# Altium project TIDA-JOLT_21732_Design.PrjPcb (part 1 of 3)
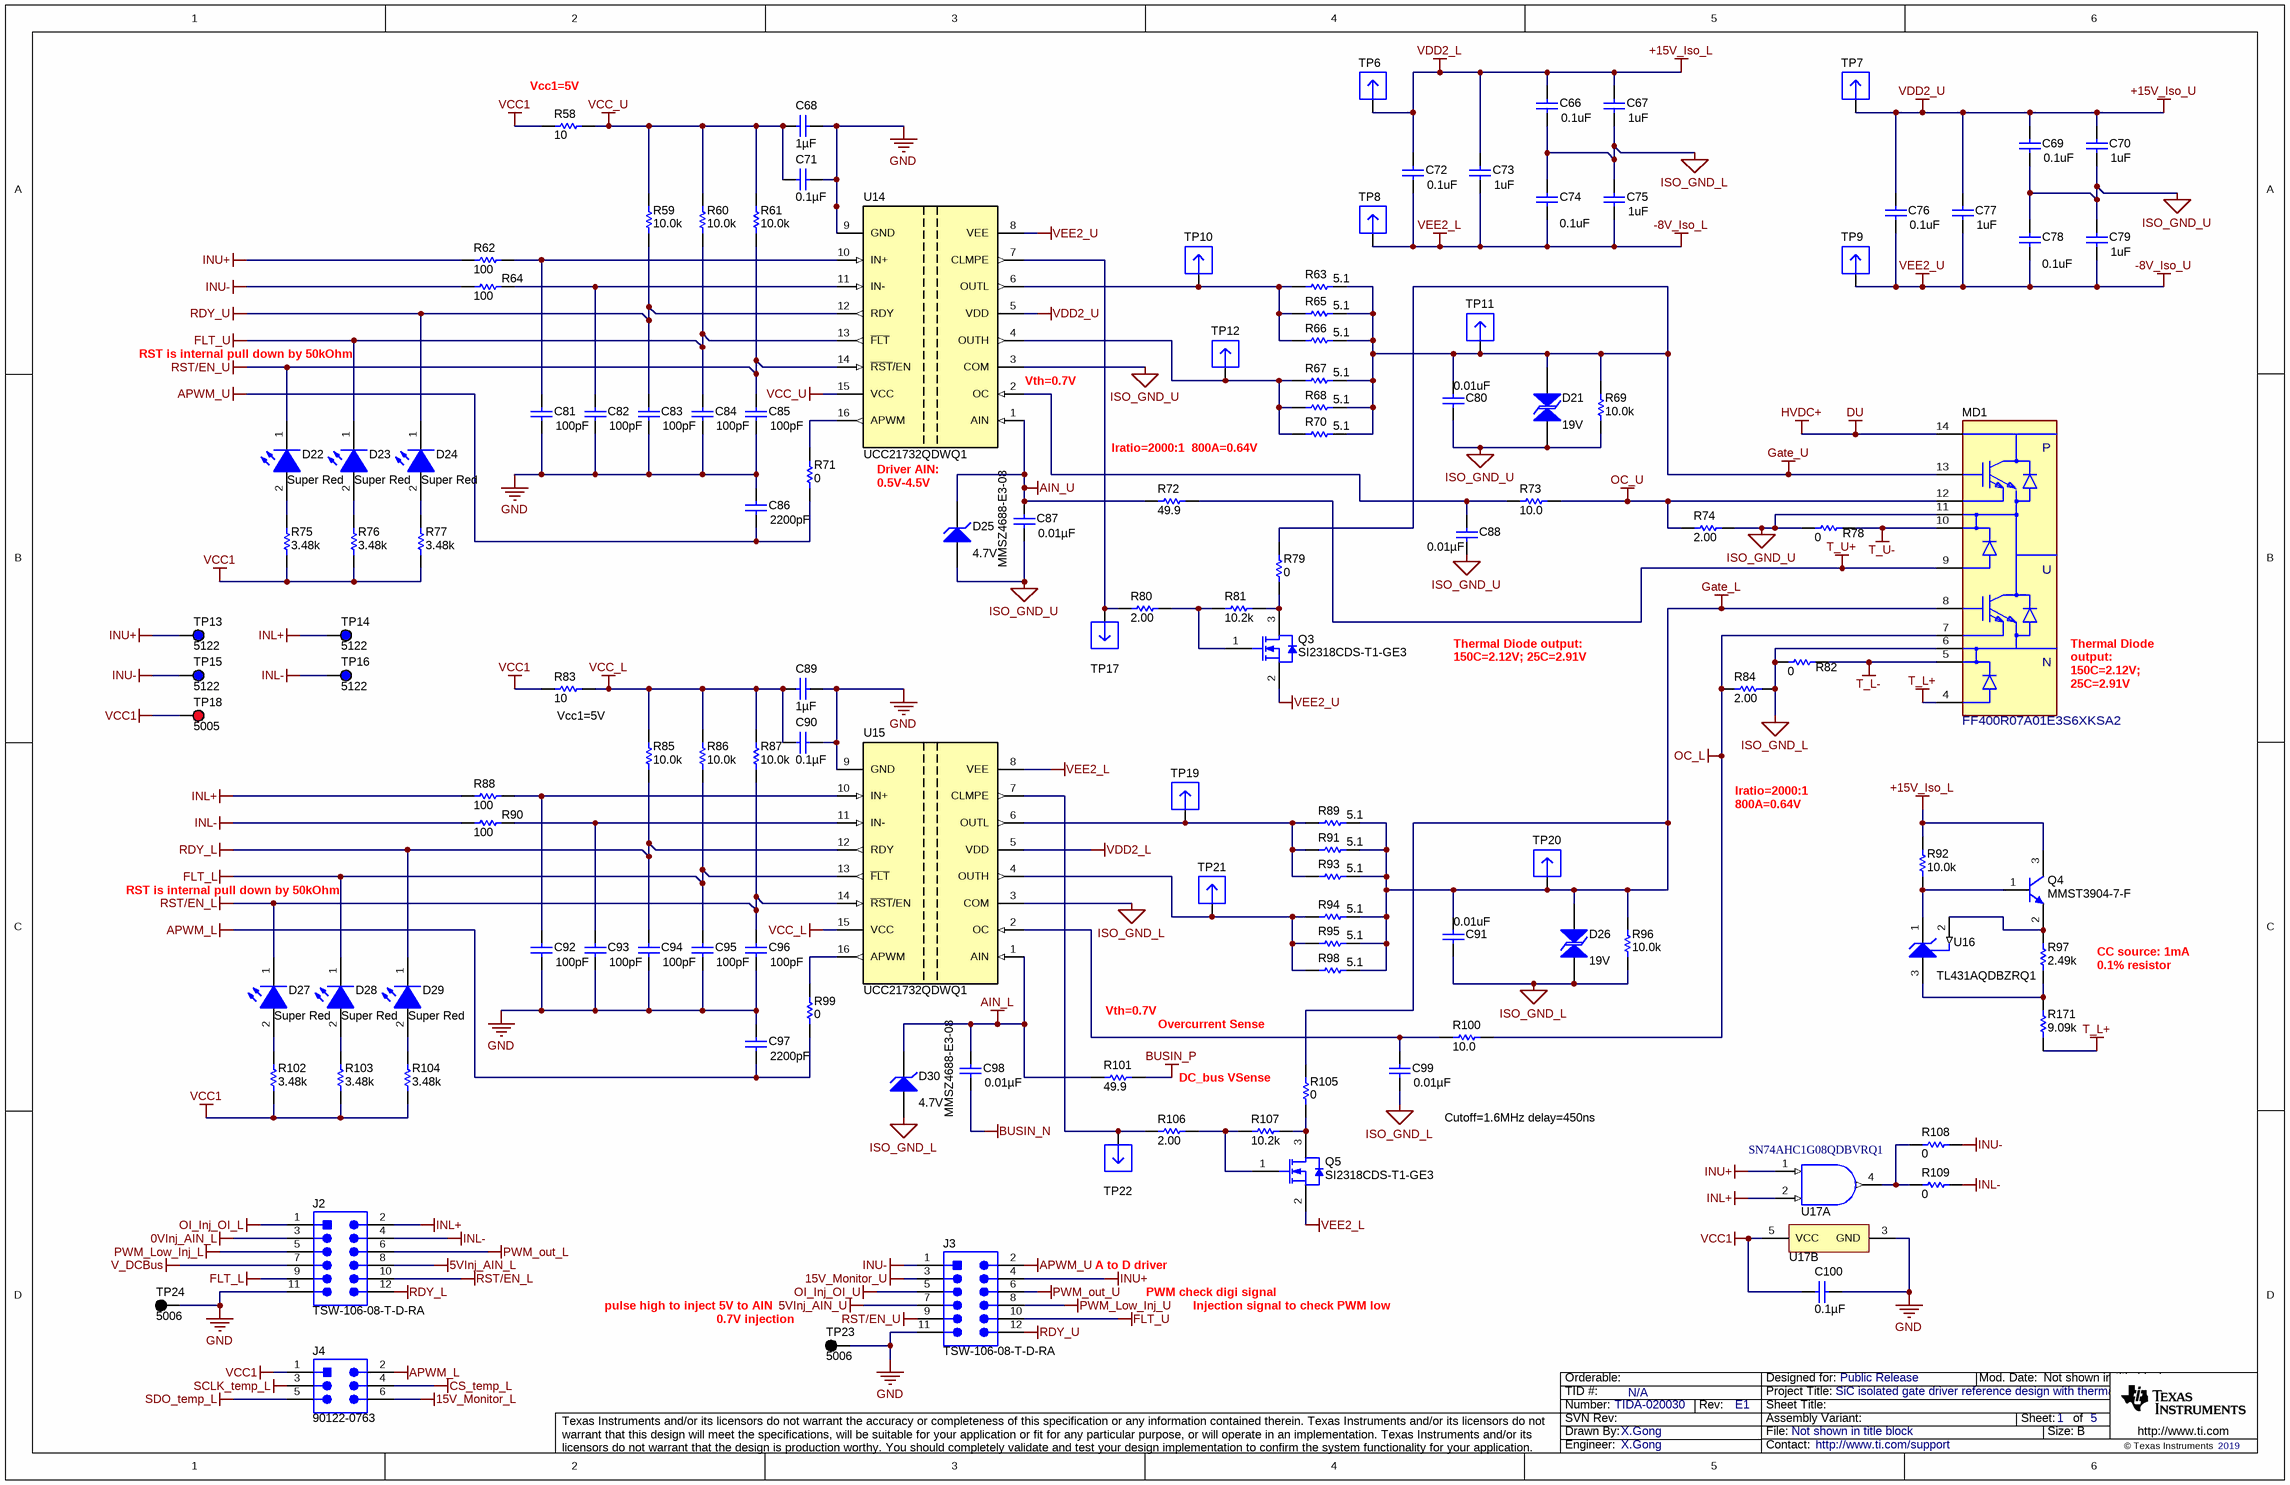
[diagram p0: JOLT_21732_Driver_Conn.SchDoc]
CopyrightYear: 2019; PCB_Layout: X.Gong; PCB_Rev: E1; PRJ_Customer: Public Release; PRJ_Engineer: X.Gong; PRJ_Number: TIDA-020030; PRJ_Title: SiC isolated gate driver reference design with thermal diode and sensing FET; SCH_Rev: E1; TechSupport: http://www.ti.com/support; TID: N/A
5 sheets, 442 parts. Net scope: global (net labels, ports and power ports of the same name join across sheets).
Board file: TIDA-JOLT_21732_Design_PCB.PcbDoc
Sheets:
  JOLT_21732_Driver_Conn.SchDoc
  JOLT_21732_OI_AIN_PWM_check.SchDoc
  JOLT_21732_DCbus_Thermal_LS.SchDoc
  JOLT_21732_Supply_Bias.SchDoc
  JOLT_21732_Design_EVM_Hardware.SchDoc

## Sheet JOLT_21732_Driver_Conn.SchDoc
size 431 x 279 mm; Date: Not shown in title block; ApprovedBy: Not shown in title block; CheckedBy: Not shown in title block; Author: Not shown in title block; CompanyName: Not shown in title block; DrawnBy: X.Gong; Engineer: Not shown in title block; Organization: Not shown in title block; Address1: Not shown in title block; Address2: Not shown in title block; Address3: Not shown in title block; Address4: Not shown in title block; DocumentNumber: 1; Revision: Use project parameter SCH_Rev; SheetNumber: 1; SheetTotal: 5; PageSetup: Record=PageOptions¦CenterHorizontal=True¦CenterVertical=True¦PrintScale=1.00¦XCorrection=1.00¦YCorrection=1.00¦PrintKind=0¦BorderSize=5000000¦LeftOffset=0¦BottomOffset=0¦Orientation=2¦PaperLength=1000¦PaperWidth=1000¦Scale=100¦PaperSource=15¦PrintQuality=600¦MediaType=1¦DitherType=10¦PaperKind=Letter¦PrintScaleMode=1

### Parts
(Parts that share a designator on the sheet are numbered #1, #2 ... from top to bottom, then left to right.)
C66  ValueDisplayed: 0.1uF  [1206]  (hidden comment: C1206C104J5RACTU)
C67  ValueDisplayed: 1uF  [1206_180]  (hidden comment: C3216X7R1H105K160AB)
C68  ValueDisplayed: 1µF  [0603]  (hidden comment: GRM188R71E105KA12D)
C69  ValueDisplayed: 0.1uF  [1206]  (hidden comment: C1206C104J5RACTU)
C70  ValueDisplayed: 1uF  [1206_180]  (hidden comment: C3216X7R1H105K160AB)
C71  ValueDisplayed: 0.1µF  [0603]  (hidden comment: GRM188R71H104KA93D)
C72  ValueDisplayed: 0.1uF  [1206]  (hidden comment: C1206C104J5RACTU)
C73  ValueDisplayed: 1uF  [1206_180]  (hidden comment: C3216X7R1H105K160AB)
C74  ValueDisplayed: 0.1uF  [0402]  (hidden comment: GCM155R71C104KA55D)
C75  ValueDisplayed: 1uF  [0603]  (hidden comment: UMK107AB7105KA-T)
C76  ValueDisplayed: 0.1uF  [1206]  (hidden comment: C1206C104J5RACTU)
C77  ValueDisplayed: 1uF  [1206_180]  (hidden comment: C3216X7R1H105K160AB)
C78  ValueDisplayed: 0.1uF  [0402]  (hidden comment: GCM155R71C104KA55D)
C79  ValueDisplayed: 1uF  [0603]  (hidden comment: UMK107AB7105KA-T)
C80  ValueDisplayed: 0.01uF  [0603]  (hidden comment: GRM188R71H103KA01D)
C81  ValueDisplayed: 100pF  [0402]  (hidden comment: CC0402JRNPO9BN101)
C82  ValueDisplayed: 100pF  [0402]  (hidden comment: CC0402JRNPO9BN101)
C83  ValueDisplayed: 100pF  [0402]  (hidden comment: CC0402JRNPO9BN101)
C84  ValueDisplayed: 100pF  [0402]  (hidden comment: CC0402JRNPO9BN101)
C85  ValueDisplayed: 100pF  [0402]  (hidden comment: CC0402JRNPO9BN101)
C86  ValueDisplayed: 2200pF  [0402]  (hidden comment: GRM155R71C222KA01D)
C87  ValueDisplayed: 0.01µF  [0603]  (hidden comment: SR0603X7R103K1NT95(F)#M123A)
C88  ValueDisplayed: 0.01µF  [0603]  (hidden comment: SR0603X7R103K1NT95(F)#M123A)
C89  ValueDisplayed: 1µF  [0603]  (hidden comment: GRM188R71E105KA12D)
C90  ValueDisplayed: 0.1µF  [0603]  (hidden comment: GRM188R71H104KA93D)
C91  ValueDisplayed: 0.01uF  [0603]  (hidden comment: GRM188R71H103KA01D)
C92  ValueDisplayed: 100pF  [0402]  (hidden comment: CC0402JRNPO9BN101)
C93  ValueDisplayed: 100pF  [0402]  (hidden comment: CC0402JRNPO9BN101)
C94  ValueDisplayed: 100pF  [0402]  (hidden comment: CC0402JRNPO9BN101)
C95  ValueDisplayed: 100pF  [0402]  (hidden comment: CC0402JRNPO9BN101)
C96  ValueDisplayed: 100pF  [0402]  (hidden comment: CC0402JRNPO9BN101)
C97  ValueDisplayed: 2200pF  [0402]  (hidden comment: GRM155R71C222KA01D)
C98  ValueDisplayed: 0.01µF  [0603]  (hidden comment: SR0603X7R103K1NT95(F)#M123A)
C99  ValueDisplayed: 0.01µF  [0603]  (hidden comment: SR0603X7R103K1NT95(F)#M123A)
C100  ValueDisplayed: 0.1µF  [0603]  (hidden comment: GRM188R71H104KA93D)
D21  value 19V  [SMB]  (hidden comment: SMBJ20CA)
D22  value Super Red  [WL-SMCW_RED]  (hidden comment: 150060SS75000)
D23  value Super Red  [WL-SMCW_RED]  (hidden comment: 150060SS75000)
D24  value Super Red  [WL-SMCW_RED]  (hidden comment: 150060SS75000)
D25  MMSZ4688-E3-08  value 4.7V  [SOD-123]
D26  value 19V  [SMB]  (hidden comment: SMBJ20CA)
D27  value Super Red  [WL-SMCW_RED]  (hidden comment: 150060SS75000)
D28  value Super Red  [WL-SMCW_RED]  (hidden comment: 150060SS75000)
D29  value Super Red  [WL-SMCW_RED]  (hidden comment: 150060SS75000)
D30  MMSZ4688-E3-08  value 4.7V  [SOD-123]
J2  TSW-106-08-T-D-RA  [AB12-DEST]
J3  TSW-106-08-T-D-RA  [AB12-DEST]
J4  90122-0763  [Molex_90122-0763]
MD1  FF400R07A01E3S6XKSA2  [FP-FF400R07A01E3S6XKSA2_PG-MDIP-14-MFG]
Q3  SI2318CDS-T1-GE3  [SOT-23]
Q4  MMST3904-7-F  [SOT-323]
Q5  SI2318CDS-T1-GE3  [SOT-23]
R58  ValueDisplayed: 10  [0805_HV]  (hidden comment: CRCW080510R0JNEA)
R59  ValueDisplayed: 10.0k  [0402]  (hidden comment: RMCF0402FT10K0)
R60  ValueDisplayed: 10.0k  [0402]  (hidden comment: RMCF0402FT10K0)
R61  ValueDisplayed: 10.0k  [0402]  (hidden comment: RMCF0402FT10K0)
R62  ValueDisplayed: 100  [0402]  (hidden comment: Resistor)
R63  ValueDisplayed: 5.1  [2010]  (hidden comment: CRCW20105R10JNEF)
R64  ValueDisplayed: 100  [0402]  (hidden comment: Resistor)
R65  ValueDisplayed: 5.1  [2010]  (hidden comment: CRCW20105R10JNEF)
R66  ValueDisplayed: 5.1  [2010]  (hidden comment: CRCW20105R10JNEF)
R67  ValueDisplayed: 5.1  [2010]  (hidden comment: CRCW20105R10JNEF)
R68  ValueDisplayed: 5.1  [2010]  (hidden comment: CRCW20105R10JNEF)
R69  ValueDisplayed: 10.0k  [0603]  (hidden comment: CRCW060310K0FKEA)
R70  ValueDisplayed: 5.1  [2010]  (hidden comment: CRCW20105R10JNEF)
R71  ValueDisplayed: 0  [0603]  (hidden comment: CRCW06030000Z0EA)
R72  ValueDisplayed: 49.9  [0603]  (hidden comment: CRCW060349R9FKEA)
R73  ValueDisplayed: 10.0  [0603]  (hidden comment: TNPW060310R0BEEA)
R74  ValueDisplayed: 2.00  [1206]  (hidden comment: CRCW12062R00FKEA)
R75  ValueDisplayed: 3.48k  [0603]  (hidden comment: CRCW06033K48FKEA)
R76  ValueDisplayed: 3.48k  [0603]  (hidden comment: CRCW06033K48FKEA)
R77  ValueDisplayed: 3.48k  [0603]  (hidden comment: CRCW06033K48FKEA)
R78  ValueDisplayed: 0  [0402]  (hidden comment: CRCW04020000Z0ED)
R79  ValueDisplayed: 0  [0603]  (hidden comment: CRCW06030000Z0EA)
R80  ValueDisplayed: 2.00  [1206]  (hidden comment: CRCW12062R00FKEA)
R81  ValueDisplayed: 10.2k  [0603]  (hidden comment: CRCW060310K2FKEA)
R82  ValueDisplayed: 0  [0402]  (hidden comment: CRCW04020000Z0ED)
R83  ValueDisplayed: 10  [0805_HV]  (hidden comment: CRCW080510R0JNEA)
R84  ValueDisplayed: 2.00  [1206]  (hidden comment: CRCW12062R00FKEA)
R85  ValueDisplayed: 10.0k  [0402]  (hidden comment: RMCF0402FT10K0)
R86  ValueDisplayed: 10.0k  [0402]  (hidden comment: RMCF0402FT10K0)
R87  ValueDisplayed: 10.0k  [0402]  (hidden comment: RMCF0402FT10K0)
R88  ValueDisplayed: 100  [0402]  (hidden comment: Resistor)
R89  ValueDisplayed: 5.1  [2010]  (hidden comment: CRCW20105R10JNEF)
R90  ValueDisplayed: 100  [0402]  (hidden comment: Resistor)
R91  ValueDisplayed: 5.1  [2010]  (hidden comment: CRCW20105R10JNEF)
R92  ValueDisplayed: 10.0k  [0805_HV]  (hidden comment: CRCW080510K0FKEA)
R93  ValueDisplayed: 5.1  [2010]  (hidden comment: CRCW20105R10JNEF)
R94  ValueDisplayed: 5.1  [2010]  (hidden comment: CRCW20105R10JNEF)
R95  ValueDisplayed: 5.1  [2010]  (hidden comment: CRCW20105R10JNEF)
R96  ValueDisplayed: 10.0k  [0603]  (hidden comment: CRCW060310K0FKEA)
R97  ValueDisplayed: 2.49k  [0805_HV]  (hidden comment: RT0805BRD072K49L)
R98  ValueDisplayed: 5.1  [2010]  (hidden comment: CRCW20105R10JNEF)
R99  ValueDisplayed: 0  [0603]  (hidden comment: CRCW06030000Z0EA)
R100  ValueDisplayed: 10.0  [0603]  (hidden comment: TNPW060310R0BEEA)
R101  ValueDisplayed: 49.9  [0603]  (hidden comment: CRCW060349R9FKEA)
R102  ValueDisplayed: 3.48k  [0603]  (hidden comment: CRCW06033K48FKEA)
R103  ValueDisplayed: 3.48k  [0603]  (hidden comment: CRCW06033K48FKEA)
R104  ValueDisplayed: 3.48k  [0603]  (hidden comment: CRCW06033K48FKEA)
R105  ValueDisplayed: 0  [0603]  (hidden comment: CRCW06030000Z0EA)
R106  ValueDisplayed: 2.00  [1206]  (hidden comment: CRCW12062R00FKEA)
R107  ValueDisplayed: 10.2k  [0603]  (hidden comment: CRCW060310K2FKEA)
R108  ValueDisplayed: 0  [0603]  (hidden comment: ERJ-3GEY0R00V)
R109  ValueDisplayed: 0  [0603]  (hidden comment: ERJ-3GEY0R00V)
R171  ValueDisplayed: 9.09k  [0603]  (hidden comment: CRCW06039K09FKEA)
TP6  0508-0-00-15-00-00-03-0  [Mill-Max_0508-0-00-15-00-00-03-0]  (value not drawn)
TP7  0508-0-00-15-00-00-03-0  [Mill-Max_0508-0-00-15-00-00-03-0]  (value not drawn)
TP8  0508-0-00-15-00-00-03-0  [Mill-Max_0508-0-00-15-00-00-03-0]  (value not drawn)
TP9  0508-0-00-15-00-00-03-0  [Mill-Max_0508-0-00-15-00-00-03-0]  (value not drawn)
TP10  0508-0-00-15-00-00-03-0  [Mill-Max_0508-0-00-15-00-00-03-0]  (value not drawn)
TP11  0508-0-00-15-00-00-03-0  [Mill-Max_0508-0-00-15-00-00-03-0]  (value not drawn)
TP12  0508-0-00-15-00-00-03-0  [Mill-Max_0508-0-00-15-00-00-03-0]  (value not drawn)
TP13  5122  [Keystone5122]
TP14  5122  [Keystone5122]
TP15  5122  [Keystone5122]
TP16  5122  [Keystone5122]
TP17  0508-0-00-15-00-00-03-0  [Mill-Max_0508-0-00-15-00-00-03-0]  (value not drawn)
TP18  5005  [Keystone5005]
TP19  0508-0-00-15-00-00-03-0  [Mill-Max_0508-0-00-15-00-00-03-0]  (value not drawn)
TP20  0508-0-00-15-00-00-03-0  [Mill-Max_0508-0-00-15-00-00-03-0]  (value not drawn)
TP21  0508-0-00-15-00-00-03-0  [Mill-Max_0508-0-00-15-00-00-03-0]  (value not drawn)
TP22  0508-0-00-15-00-00-03-0  [Mill-Max_0508-0-00-15-00-00-03-0]  (value not drawn)
TP23  5006  [Keystone5006]
TP24  5006  [Keystone5006]
U14  UCC21732QDWQ1  [DW0016B_HV]
U15  UCC21732QDWQ1  [DW0016B_HV]
U16  TL431AQDBZRQ1  [DBZ0003A_N]
U17#1  SN74AHC1G08QDBVRQ1  [DBV0005A_N]  (part A of 2)
U17#2  SN74AHC1G08QDBVRQ1  [DBV0005A_N]  (value not drawn)  (part B of 2)

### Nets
0VInj_AIN_L: J2.3
5VInj_AIN_L: J2.8
5VInj_AIN_U: J3.7
15V_Monitor_L: J4.6
15V_Monitor_U: J3.3
+15V_Iso_L: C66.1 C67.1 C72.1 C73.1 Q4.3(C) R92.2 TP6.1 U15.5(VDD)  [also labelled VDD2_L]
+15V_Iso_U: C69.1 C70.1 C76.1 C77.1 TP7.1 U14.5(VDD)  [also labelled VDD2_U]
-8V_Iso_L: C72.2 C73.2 C74.2 C75.2 Q5.2(S) TP8.1 U15.8(VEE)  [also labelled VEE2_L]
-8V_Iso_U: C76.2 C77.2 C78.2 C79.2 Q3.2(S) TP9.1 U14.8(VEE)  [also labelled VEE2_U]
AIN_L: C98.1 D30.1(K) R101.2 U15.1(AIN)
AIN_U: C87.1 D25.1(K) R72.2 U14.1(AIN)
APWM_L: C97.1 J4.2 R99.1
APWM_U: C86.1 J3.2 R71.1
BUSIN_N: C98.2
BUSIN_P: R101.1
CS_temp_L: J4.4
DU: MD1.14(PS)  [also labelled HVDC+]
FLT_L: C95.1 D28.1(K) J2.9 R86.1 U15.13(~{FLT})
FLT_U: C84.1 D23.1(K) J3.10 R60.1 U14.13(~{FLT})
Gate_L: C91.1 D26.2 MD1.8(GL) R89.2 R91.2 R93.2 R94.2 R95.2 R96.2 R98.2 R105.2 TP20.1
Gate_U: C80.1 D21.2 MD1.13(GH) R63.2 R65.2 R66.2 R67.2 R68.2 R69.2 R70.2 R79.2 TP11.1
GND: C68.1 C71.2 C81.2 C82.2 C83.2 C84.2 C85.2 C86.2 C89.1 C90.2 C92.2 C93.2 C94.2 C95.2 C96.2 C97.2 C100.2 J2.11 J3.11 TP23.1 TP24.1 U14.9(GND) U15.9(GND) U17#2.3(GND)
INL+: J2.2 R88.2 TP14.1 U17#1.2(B)
INL-: J2.4 R90.2 R109.2 TP16.1
INU+: J3.4 R62.2 TP13.1 U17#1.1(A)
INU-: J3.1 R64.2 R108.2 TP15.1
ISO_GND_L: C66.2 C67.2 C74.1 C75.1 C91.2 C99.2 D26.1 D30.2(A) MD1.6(EL) R82.1 R84.1 R96.1 U15.3(COM)
ISO_GND_U: C69.2 C70.2 C78.1 C79.1 C80.2 C87.2 C88.2 D21.1 D25.2(A) MD1.11(EH) R69.1 R74.1 R78.1 U14.3(COM)
OC_L: MD1.7(CSL) R84.2 R100.2
OC_U: MD1.12(CSH) R73.2 R74.2
OI_Inj_OI_L: J2.1
OI_Inj_OI_U: J3.5
PWM_Low_Inj_L: J2.5
PWM_Low_Inj_U: J3.8
PWM_out_L: J2.6
PWM_out_U: J3.6
RDY_L: C94.1 D29.1(K) J2.12 R85.1 U15.12(RDY)
RDY_U: C83.1 D24.1(K) J3.12 R59.1 U14.12(RDY)
RST/EN_L: C96.1 D27.1(K) J2.10 R87.1 U15.14(~{RST}/EN)
RST/EN_U: C85.1 D22.1(K) J3.9 R61.1 U14.14(~{RST}/EN)
SCLK_temp_L: J4.3
SDO_temp_L: J4.5
T_L+: MD1.4(T+L) R171.1
T_L-: MD1.5(T-L) R82.2
T_U+: MD1.9(T+H) R72.1
T_U-: MD1.10(T-H) R78.2
V_DCBus: J2.7
VCC1: C100.1 J4.1 R58.1 R75.1 R76.1 R77.1 R83.1 R102.1 R103.1 R104.1 TP18.1 U17#2.5(VCC)
VCC_L: C89.2 C90.1 R83.2 R85.2 R86.2 R87.2 U15.15(VCC)
VCC_U: C68.2 C71.1 R58.2 R59.2 R60.2 R61.2 U14.15(VCC)
NetC81_1: C81.1 R62.1 U14.10(IN+)
NetC82_1: C82.1 R64.1 U14.11(IN-)
NetC88_1: C88.1 R73.1 U14.2(OC)
NetC92_1: C92.1 R88.1 U15.10(IN+)
NetC93_1: C93.1 R90.1 U15.11(IN-)
NetC99_1: C99.1 R100.1 U15.2(OC)
NetD22_2: D22.2(A) R75.2
NetD23_2: D23.2(A) R76.2
NetD24_2: D24.2(A) R77.2
NetD27_2: D27.2(A) R102.2
NetD28_2: D28.2(A) R103.2
NetD29_2: D29.2(A) R104.2
NetQ3_1: Q3.1(G) R80.1 R81.1
NetQ3_3: Q3.3(D) R79.1 R81.2
NetQ4_1: Q4.1(B) R92.1 U16.1(CATHODE)
NetQ4_2: Q4.2(E) R97.2 U16.2(REF)
NetQ5_1: Q5.1(G) R106.1 R107.1
NetQ5_3: Q5.3(D) R105.1 R107.2
NetR63_1: R63.1 R65.1 R66.1 TP10.1 U14.6(OUTL)
NetR67_1: R67.1 R68.1 R70.1 TP12.1 U14.4(OUTH)
NetR71_2: R71.2 U14.16(APWM)
NetR80_2: R80.2 TP17.1 U14.7(CLMPE)
NetR89_1: R89.1 R91.1 R93.1 TP19.1 U15.6(OUTL)
NetR94_1: R94.1 R95.1 R98.1 TP21.1 U15.4(OUTH)
NetR97_1: R97.1 R171.2 U16.3(ANODE)
NetR99_2: R99.2 U15.16(APWM)
NetR106_2: R106.2 TP22.1 U15.7(CLMPE)
NetR108_1: R108.1 R109.1 U17#1.4(Y)

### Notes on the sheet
- (near R58) Vcc1=5V
- RST is internal pull down by 50kOhm
- (near U14) Vth=0.7V
- Driver AIN:
  0.5V-4.5V
- Iratio=2000:1  800A=0.64V
- Thermal Diode output:
  150C=2.12V; 25C=2.91V
- (near R83) Vcc1=5V
- Iratio=2000:1
  800A=0.64V
- Vth=0.7V
- Overcurrent Sense
- CC source: 1mA
  0.1% resistor
- DC_bus VSense
- Cutoff=1.6MHz delay=450ns
- pulse high to inject 5V to AIN
- A to D driver
- PWM check digi signal
- Injection signal to check PWM low
- (near TP23) 0.7V injection

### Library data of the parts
C66 C69 C72 C76 = CMP-0008584-2: CAP, CERM, 0.1 uF, 50 V, +/- 5%, X7R, 1206; Manufacturer: Kemet; TaMin_C: -55°C; ESR_ohm: 0.059; Polarized: N; SizeAreaWB_mm2: 10.92; Value1: 0.059 ohm; U/M: EA; Value: 0.1uF; TaMax_C: 125°C; SizeZ_mm: 1.35; SizeX_mm: 3.2; SizeY_mm: 1.6; Value2: 50V; SizeArea_mm2: 5.12; Cap_F: 100nF; IRMS_A: 1.2A; AEC Category: Q200
C67 C70 C73 C77 = CMP-0008695-2: CAP, CERM, 1 uF, 50 V, +/- 10%, X7R, 1206; Manufacturer: TDK; TaMin_C: -55°C; ESR_ohm: 9.289m; Polarized: N; SizeAreaWB_mm2: 10.92; Value1: 0.009289 ohm; U/M: EA; Value: 1uF; TaMax_C: 125°C; SizeZ_mm: 1.8; SizeX_mm: 3.2; SizeY_mm: 1.6; Value2: 50V; SizeArea_mm2: 5.12; CompType: Capacitor; Cap_F: 1µF; IRMS_A: 2.38446A; AEC Category: Q200
C68 C89 = GRM188R71E105KA12D: CAP, CERM, 1 µF, 25 V,+/- 10%, X7R, 0603; Manufacturer: MuRata; Polarized: N; CompType: Capacitor; Value: 1uF; U/M: EA; Cap_F: 0.000001; Tolerance_%: 10; VDC_V: 25; Value2: 25V; TaMin_C: -55; TaMax_C: 125; SizeArea_mm2: 1.28; SizeAreaWB_mm2: 4.68; SizeX_mm: 1.6; SizeY_mm: 0.8; SizeZ_mm: 1; AEC Category: Q200; Green_Lifecycle: Active; Green_REACh: Passed
C71 C90 C100 = GRM188R71H104KA93D: CAP, CERM, 0.1 µF, 50 V,+/- 10%, X7R, 0603; Manufacturer: MuRata; Polarized: N; CompType: Capacitor; Value: 0.1uF; U/M: EA; Cap_F: 0.0000001; Tolerance_%: 10; VDC_V: 50; Value2: 50V; TaMin_C: -55; TaMax_C: 125; SizeArea_mm2: 1.28; SizeAreaWB_mm2: 4.68; SizeX_mm: 1.6; SizeY_mm: 0.8; SizeZ_mm: 1; AEC Category: Q200; Green_Lifecycle: Active; Green_REACh: Passed
C74 C78 = CMP-0006351-2: CAP, CERM, 0.1 uF, 16 V, +/- 10%, X7R, 0402; Manufacturer: MuRata; TaMin_C: -55°C; Polarized: N; SizeAreaWB_mm2: 3; Value1: Unknown; U/M: EA; Value: 0.1uF; TaMax_C: 125°C; SizeZ_mm: 0.6; SizeX_mm: 1; SizeY_mm: 0.5; Value2: 16V; CompType: Capacitor; Cap_F: 100nF; AEC Category: Q200
C75 C79 = CMP-0006867-4: CAP, CERM, 1 uF, 25 V, +/- 10%, X7R, 0603; Manufacturer: Kemet; PartNumber: C0603C105K3RACTU; TaMin_C: -55°C; Polarized: N; SizeAreaWB_mm2: 4.68; Value1: Unknown; U/M: EA; Value: 1uF; TaMax_C: 125°C; SizeZ_mm: 1; SizeX_mm: 1.6; SizeY_mm: 0.8; Value2: 25V; SizeArea_mm2: 1.28; CompType: Capacitor; Cap_F: 1µF; AEC Category: Q200
C80 C91 = CMP-0007433-1: CAP, CERM, 0.01 uF, 50 V, +/- 10%, X7R, 0603; Manufacturer: MuRata; TaMin_C: -55°C; Polarized: N; SizeAreaWB_mm2: 4.68; Value1: Unknown; U/M: EA; Value: 0.01uF; TaMax_C: 125°C; SizeZ_mm: 1; SizeX_mm: 1.6; SizeY_mm: 0.8; Value2: 50V; SizeArea_mm2: 1.28; CompType: Capacitor; Cap_F: 10nF; AEC Category: Q200
C81-C85 C92-C96 = CMP-0006303-2: CAP, CERM, 100 pF, 50 V, +/- 5%, C0G/NP0, 0402; Manufacturer: Yageo America; TaMin_C: -55°C; Polarized: N; SizeAreaWB_mm2: 3; Value1: Unknown; U/M: EA; Value: 100pF; TaMax_C: 125°C; SizeZ_mm: 0.6; SizeX_mm: 1; SizeY_mm: 0.5; Value2: 50V; CompType: Capacitor; AEC Category: Q200
C86 C97 = CMP-0006646-2: CAP, CERM, 2200 pF, 16 V, +/- 10%, X7R, 0402; Manufacturer: MuRata; TaMin_C: -55°C; Polarized: N; SizeAreaWB_mm2: 3; Value1: Unknown; U/M: EA; Value: 2200pF; TaMax_C: 125°C; SizeZ_mm: 0.6; SizeX_mm: 1; SizeY_mm: 0.5; Value2: 16V; Cap_F: 2.2nF; AEC Category: Q200
C87 C88 C98 C99 = CMP-0079721-1: CAP, CERM, 0.01 µF, 25 V,+/- 10%, X7R, 0603; Manufacturer: Presidio Components; TaMin_C: -55°C; Polarized: N; SizeAreaWB_mm2: 4.68; U/M: EA; Value: 0.01uF; TaMax_C: 125°C; SizeZ_mm: 1; SizeX_mm: 1.6; SizeY_mm: 0.8; Value2: 25V; SizeArea_mm2: 1.28; CompType: Capacitor; Cap_F: 10nF; AEC Category: Q200
D21 D26 = CMP-0005553-2: Diode, TVS, Bi, 19 V, SMB; Manufacturer: Littelfuse; Power_W: 5W; SizeAreaWB_mm2: 44.156; RJA_CperW: 100; U/M: EA; SizeZ_mm: 2.6; SizeX_mm: 5.6; SizeY_mm: 3.81; SizeArea_mm2: 21.336; AEC Category: Q101
D22-D24 D27-D29 = CMP-0002893-1: LED, Super Red, SMD; Manufacturer: Wurth Elektronik; Io_A: 20mA; Value1: W; U/M: EA; Vf_V: 1.9V; Type: AlInGaP
D25 D30 = CMP-0077598-3: Diode, Zener, 4.7 V, 500 mW, SOD-123; Manufacturer: Vishay-Semiconductor; SizeArea_mm2: 6.545; SizeAreaWB_mm2: 13.095; SizeX_mm: 3.85; Power_W: 500mW; AEC Category: Q101; AEC Qualified: N; Value1: 0.5W; RJA_CperW: 340; SizeY_mm: 1.7; SizeZ_mm: 1.35
J2 J3 = CMP-0075545-2: Header, 2.54 mm, 6x2, Gold, R/A,TH; Manufacturer: Samtec; Pitch_mm: 2.54; Cert_VDE: N; Gender: Male; Cert_CSA: Y; Current_A: 6.3A; Voltage_V: 550V; ContactFinish: Tin; Row_Count: 2
J4 = CMP-0077741-2: Header, 2.54mm, 3x2, Gold, R/A, TH; Manufacturer: Molex; Pitch_mm: 2.54; Gender: Male; Cert_UL: Y; Current_A: 3A; Voltage_V: 350V; Shrouded: N; Row_Count: 2
MD1 = CMP-0086469-1: MOD IGBT MED PWR 14MDIP; Manufacturer: Infineon Technologies; AEC Qualified: Yes; SizeZ_mm: 71.8mm
Q3 Q5 = CMP-0000739-1: MOSFET, N-CH, 40 V, 5.6 A, SOT-23; Alternate Manufacturer: None; Manufacturer: Vishay-Siliconix; SizeZ_mm: 1.1; ChType: N; Value2: 5.8 nC; Value1: 0.05; VdsMax_V: 40V; SizeX_mm: 2.5; SizeY_mm: 3; Vgs_V: 20V; Value: 40V; Rdson45_ohm: 0.051; SizeArea_mm2: 7.5; AEC Category: Q101; IdsMax_A: 5.6A; SizeAreaWB_mm2: 14; U/M: EA; QgTyp_nC: 5.8
Q4 = CMP-0000406-2: Transistor, NPN, 40 V, 0.2 A, SOT-323; Manufacturer: Diodes Inc.; TaMax_C: 150°C; Value2: 400; Value1: 0.2 A; Vcesat1_V: 3dV; SizeX_mm: 2.2; TaMin_C: -55°C; IcRated_A: 2dA; CompType: BJT; SizeZ_mm: 1.1; Value: 40 V; SizeArea_mm2: 4.84; NPN: 1; Vceo_V: 40V; PNP: 0; AEC Category: Q101; SizeAreaWB_mm2: 10.24; U/M: EA
R58 R83 = CRCW080510R0JNEA: RES, 10, 5%, 0.125 W, 0805; Manufacturer: Vishay-Dale; CompType: Resistor; Value: 10; Value_Code: 10R0; Tolerance_%: 5; Power_W: 0.125; Value2: 0.125W; VDC_V: 150; TempCo: 200 ppm/C; SizeArea_mm2: 2.5; SizeX_mm: 2; SizeY_mm: 1.25; SizeZ_mm: 1.45; EIA_Code: E24; U/M: EA; AEC Category: Q200; Green_Lifecycle: Active; Green_REACh: Passed
R59-R61 R85-R87 = CMP-0026754-1: RES, 10.0 k, 1%, 0.063 W, AEC-Q200 Grade 0, 0402; Manufacturer: Stackpole Electronics Inc; Power_W: 63mW; TempCo: 100 ppm/C; Value_Code: 10k0; U/M: EA; Value: 10.0k; EIA_Code: E96; Res_ohm: 10k; SizeX_mm: 1; SizeY_mm: 0.5; SizeZ_mm: 0.6; Value2: 0.063W; CompType: Resistor; AEC Qualified: Y; VDC_V: 50V; AEC Grade: 0; AEC Category: Q200
R62 R64 R88 R90 = CMP-0025951-2: RES, 100, 1%, 0.063 W, 0402; PartNumber: CRCW0402100RFKED; Manufacturer: Vishay-Dale; Value: 100; Value_Code: 100R; Power_W: 63mW; Value2: 0.063W; VDC_V: 50V; TempCo: 100 ppm/C; SizeArea_mm2: 0.5; SizeX_mm: 1; SizeZ_mm: 0.6; EIA_Code: E96; U/M: EA; AEC Category: Q200
R63 R65-R68 R70 R89 R91 R93-R95 R98 = CRCW20105R10JNEF: RES, 5.1, 5%, 0.75 W, AEC-Q200 Grade 0, 2010; Manufacturer: Vishay-Dale; CompType: Resistor; Value: 5.1; Value_Code: 5R10; Tolerance_%: 5; Power_W: 0.75; Value2: 0.75W; VDC_V: 400; TempCo: 200 ppm/C; SizeArea_mm2: 12.5; SizeY_mm: 2.5; SizeZ_mm: 1.66; EIA_Code: E24; U/M: EA; AEC Category: Q200; AEC Qualified: Y; AEC Grade: 0
R69 R96 = CRCW060310K0FKEA: RES, 10.0 k, 1%, 0.1 W, 0603; Manufacturer: Vishay-Dale; CompType: Resistor; Value: 10.0k; Res_ohm: 10000; Value_Code: 10k0; Tolerance_%: 1; Power_W: 0.1; Value2: 0.1W; VDC_V: 75; TempCo: 100 ppm/C; SizeArea_mm2: 1.28; SizeX_mm: 1.6; SizeY_mm: 0.8; EIA_Code: E96; U/M: EA; AEC Category: Q200; Green_Lifecycle: Active; Green_REACh: Passed
R71 R79 R99 R105 = CRCW06030000Z0EA: RES, 0, 5%, 0.1 W, 0603; Manufacturer: Vishay-Dale; CompType: Resistor; Value: 0; Value_Code: 0000; Tolerance_%: 5; Power_W: 0.1; Value2: 0.1W; VDC_V: 75; TempCo: 200 ppm/C; SizeArea_mm2: 1.28; SizeX_mm: 1.6; SizeY_mm: 0.8; SizeZ_mm: 1; EIA_Code: E24; U/M: EA; AEC Category: Q200; Green_Lifecycle: Active; Green_REACh: Passed
R72 R101 = CRCW060349R9FKEA: RES, 49.9, 1%, 0.1 W, 0603; Manufacturer: Vishay-Dale; CompType: Resistor; Value: 49.9; Value_Code: 49R9; Tolerance_%: 1; Power_W: 0.1; Value2: 0.1W; VDC_V: 75; TempCo: 100 ppm/C; SizeArea_mm2: 1.28; SizeX_mm: 1.6; SizeY_mm: 0.8; EIA_Code: E96; U/M: EA; AEC Category: Q200; Green_Lifecycle: Active; Green_REACh: Passed
R73 R100 = TNPW060310R0BEEA: RES, 10.0, 0.1%, 0.1 W, 0603; Manufacturer: Vishay-Dale; CompType: Resistor; Value: 10.0; Res_ohm: 10; Value_Code: 10R0; Tolerance_%: 0.1; Value2: 0.1W; VDC_V: 75; TempCo: 25 ppm/C; SizeArea_mm2: 1.28; SizeX_mm: 1.6; SizeY_mm: 0.8; SizeZ_mm: 1; EIA_Code: E192; U/M: EA; AEC Category: Q200; Green_Lifecycle: Active; Green_REACh: Passed
R74 R80 R84 R106 = CRCW12062R00FKEA: RES, 2.00, 1%, 0.25 W, 1206; Manufacturer: Vishay-Dale; CompType: Resistor; Value: 2.00; Res_ohm: 2; Value_Code: 2R00; Tolerance_%: 1; Power_W: 0.25; Value2: 0.25W; VDC_V: 200; TempCo: 100 ppm/C; SizeArea_mm2: 5.12; SizeX_mm: 3.2; SizeY_mm: 1.6; SizeZ_mm: 1.35; EIA_Code: E96; U/M: EA; AEC Category: Q200; Green_Lifecycle: Active; Green_REACh: Passed
R75-R77 R102-R104 = CRCW06033K48FKEA: RES, 3.48 k, 1%, 0.1 W, 0603; Manufacturer: Vishay-Dale; CompType: Resistor; Value: 3.48k; Res_ohm: 3480; Value_Code: 3k48; Tolerance_%: 1; Power_W: 0.1; Value2: 0.1W; VDC_V: 75; TempCo: 100 ppm/C; SizeArea_mm2: 1.28; SizeX_mm: 1.6; SizeY_mm: 0.8; EIA_Code: E96; U/M: EA; AEC Category: Q200; Green_Lifecycle: Active; Green_REACh: Passed
R78 R82 = CMP-0026822-3: RES, 0, 5%, 0.063 W, AEC-Q200 Grade 0, 0402; Manufacturer: Vishay-Dale; Power_W: 63mW; TempCo: 200 ppm/C; Value_Code: 0000; Value: 0; EIA_Code: E24; SizeX_mm: 1; SizeY_mm: 0.5; SizeZ_mm: 0.6; Value2: 0.063W; CompType: Resistor; AEC Qualified: Y; VDC_V: 50V; AEC Category: Q200
R81 R107 = CRCW060310K2FKEA: RES, 10.2 k, 1%, 0.1 W, 0603; Manufacturer: Vishay-Dale; CompType: Resistor; Value: 10.2k; Res_ohm: 10200; Value_Code: 10k2; Tolerance_%: 1; Power_W: 0.1; Value2: 0.1W; VDC_V: 75; TempCo: 100 ppm/C; SizeArea_mm2: 1.28; SizeX_mm: 1.6; SizeY_mm: 0.8; EIA_Code: E96; U/M: EA; AEC Category: Q200; Green_Lifecycle: Active; Green_REACh: Passed
R92 = CRCW080510K0FKEA: RES, 10.0 k, 1%, 0.125 W, 0805; Manufacturer: Vishay-Dale; CompType: Resistor; Value: 10.0k; Res_ohm: 10000; Value_Code: 10k0; Tolerance_%: 1; Power_W: 0.125; Value2: 0.125W; VDC_V: 150; TempCo: 100 ppm/C; SizeArea_mm2: 2.5; SizeX_mm: 2; SizeY_mm: 1.25; SizeZ_mm: 1.45; EIA_Code: E96; U/M: EA; AEC Category: Q200; Green_Lifecycle: Active; Green_REACh: Passed
R97 = RT0805BRD072K49L: RES, 2.49 k, 0.1%, 0.125 W, 0805; Manufacturer: Yageo America; CompType: Resistor; Value: 2.49k; Res_ohm: 2490; Value_Code: 2k49; Tolerance_%: 0.1; Power_W: 0.125; Value2: 0.125W; VDC_V: 150; TempCo: 25 ppm/C; SizeArea_mm2: 2.5; SizeX_mm: 2; SizeY_mm: 1.25; SizeZ_mm: 1.45; EIA_Code: E192; U/M: EA; AEC Category: Q200
R108 R109 = CMP-0025874-3: RES, 0, 5%, 0.1 W, 0603; Manufacturer: Panasonic; Power_W: 100mW; TempCo: 600 ppm/C; Value_Code: 0000; U/M: EA; Value: 0; EIA_Code: E24; SizeX_mm: 1.6; SizeY_mm: 0.8; SizeZ_mm: 1; Value2: 0.1W; SizeArea_mm2: 1.28; VDC_V: 50V; AEC Category: Q200
R171 = CRCW06039K09FKEA: RES, 9.09 k, 1%, 0.1 W, 0603; Manufacturer: Vishay-Dale; CompType: Resistor; Value: 9.09k; Res_ohm: 9090; Value_Code: 9k09; Tolerance_%: 1; Power_W: 0.1; Value2: 0.1W; VDC_V: 75; TempCo: 100 ppm/C; SizeArea_mm2: 1.28; SizeX_mm: 1.6; SizeY_mm: 0.8; EIA_Code: E96; U/M: EA; AEC Category: Q200; Green_Lifecycle: Active; Green_REACh: Passed
TP6-TP12 TP17 TP19-TP22 = CMP-0055027-1: PCB Pin, 20mil Dia, Gold, TH; Manufacturer: Mill-Max; CNHeader: FALSE; Gender: Male; CompType: PCB Pin
TP13-TP16 = CMP-0055155-1: Test Point, Compact, Blue, TH; Manufacturer: Keystone; CNHeader: FALSE; Green_Lifecycle: Active; Green_REACh: Passed; ContactFinish: Silver; CT: TRUE
TP18 = CMP-0055142-1: Test Point, Compact, Red, TH; Manufacturer: Keystone; CNHeader: FALSE; Green_Lifecycle: Active; Green_REACh: Passed; ContactFinish: Silver; CT: TRUE
TP23 TP24 = CMP-0055143-1: Test Point, Compact, Black, TH; Manufacturer: Keystone; CNHeader: FALSE; Green_Lifecycle: Active; Green_REACh: Passed; ContactFinish: Silver; CT: TRUE
U14 U15 = CMP-0080538-2: Single Channel Isolated Gate Driver for SiC/IGBT with Advanced Protection and High-CMTI, DW0016B (SOIC-16); Alternate PartNumber: UCC21732QDWRQ1; Alternate Manufacturer: Texas Instruments; SizeY_mm: 10.3; SizeX_mm: 10.4; CompType: IC; SizeArea_mm2: 107.12; SizeAreaWB_mm2: 152.52; AEC Category: Q200; SizeZ_mm: 2.65; AEC Qualified: Y
U16 = CMP-0033164-1: Automotive Catalog Adjustable Precision Shunt Regulator, 34 ppm / degC, 100 mA, -40 to 125 degC, 3-pin SOT-23 (DBZ), Green (RoHS & no Sb/Br); Manufacturer: Texas Instruments; SubFamily: Shunt Voltage Reference; Initial Accuracy @ 25/deg C(%): 1; Min Iz for Regulation(uA): 600; Iout/Iz(Max)(mA): 100; Temp Coeff(Typ)(ppm/ degree C): 34; VO Adj(Max)(V): 36; VO Adj(Min)(V): 2.495
U17#1 U17#2 = CMP-0051573-1: Automotive Catalog Single 2-Input Positive-AND Gate, DBV0005A, LARGE T&R; Generic Part Number: SN74AHC1G08-Q1; Manufacturer: Texas Instruments; Output Drive (IOL/IOH)(Max)(mA): 50/-50; Output Type: CMOS; Logic: True; Bits(#): 1; Schmitt Trigger: No; Technology Family: AHC; VCC(Max)(V): 5.5; Gate Type: AND; VCC(Min)(V): 2; Voltage(Nom)(V): 3.3,5; tpd @ Nom Voltage(Max)(ns): 12.3,7.9; F @ Nom Voltage(Max)(Mhz): 75; ICC @ Nom Voltage(Max)(mA): 0.01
